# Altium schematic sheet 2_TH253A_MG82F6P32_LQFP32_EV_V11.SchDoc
size 292 x 203 mm
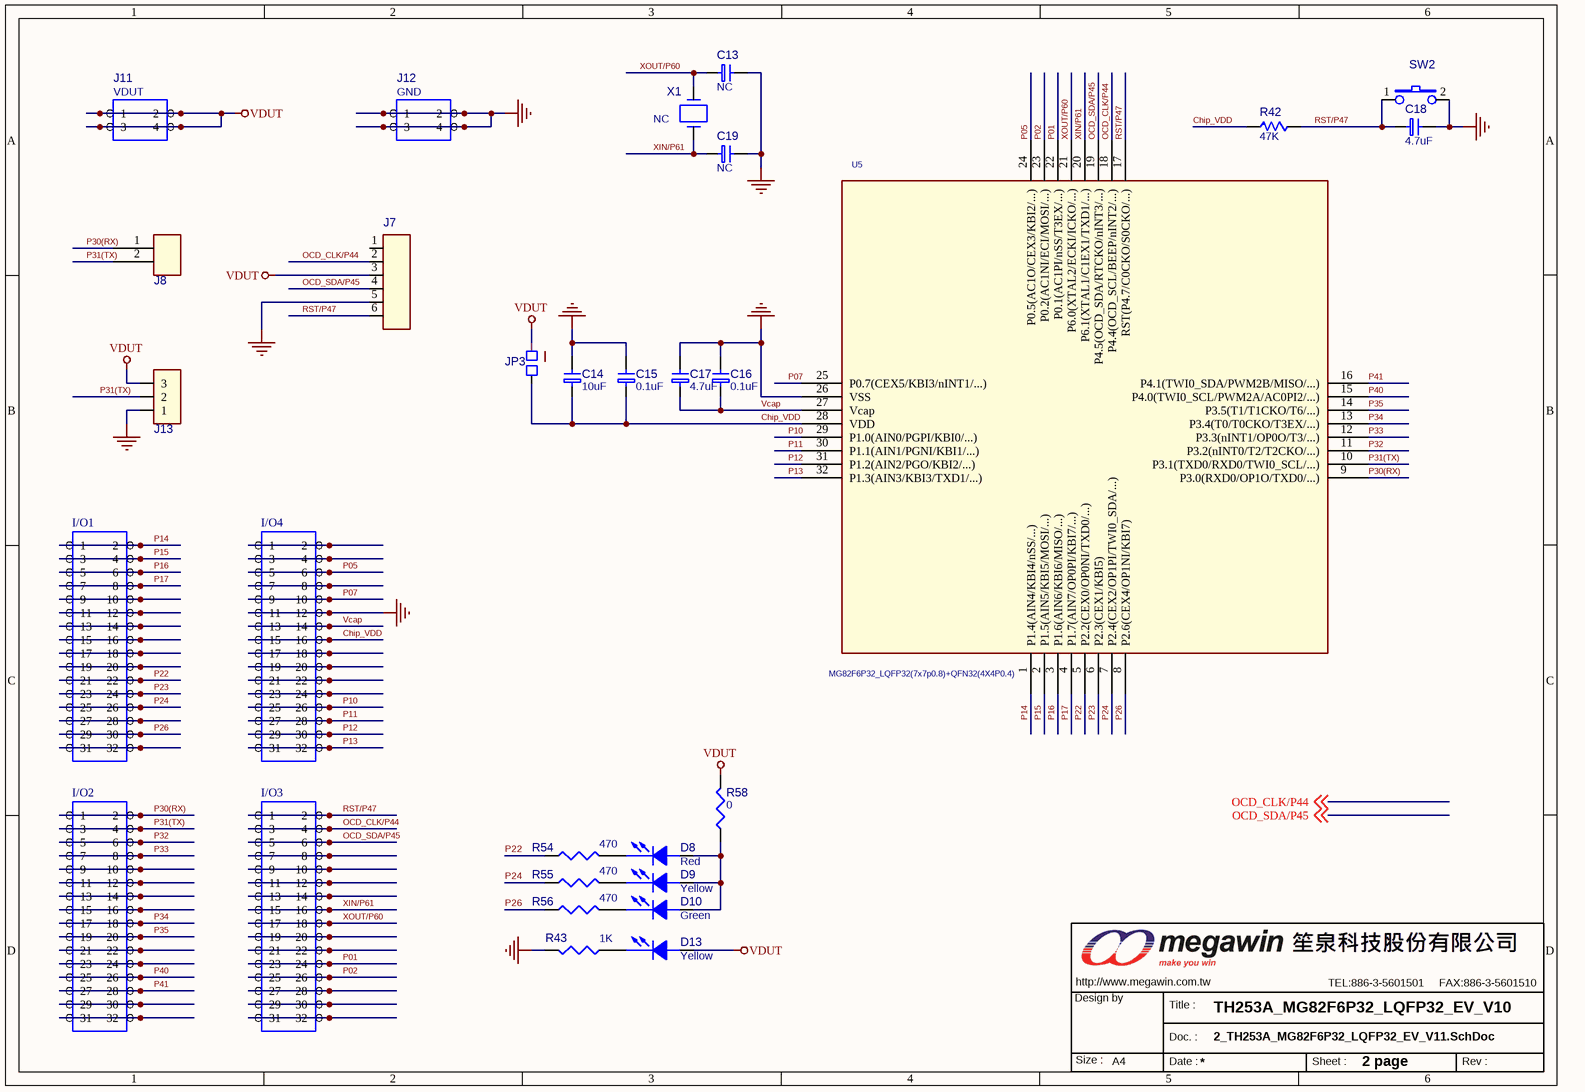
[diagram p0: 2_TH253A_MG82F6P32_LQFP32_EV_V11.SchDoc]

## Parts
C13  NC  [0603C]
C14  10uF  [0603C]
C15  0.1uF  [0603C]
C16  0.1uF  [0603C]
C17  4.7uF  [0603C]
C18  4.7uF  [0603C]
C19  NC  [0603C]
D8  Red  [LED38+0805]
D9  Yellow  [LED38+0805]
D10  Green  [LED38+0805]
D13  Yellow  [0805D]
I/O1  CON16X2  [PS16X2P254]  (value not drawn)
I/O2  CON16X2  [PS16X2P254]  (value not drawn)
I/O3  CON16X2  [PS16X2P254]  (value not drawn)
I/O4  CON16X2  [PS16X2P254]  (value not drawn)
J7  CON6  [PS6P254]  (value not drawn)
J8  NC  [PS2P254]  (value not drawn)
J11  VDUT  [PS2X2P254]
J12  GND  [PS2X2P254]
J13  3P2.54_F_90  [PS3P254f_90]  (value not drawn)
JP3  JUMPER_2  [PS2P254]  (value not drawn)
MW1  OrgAddr3: TEL:886-3-5601501     FAX:886-3-5601510  [MEGAWIN_3.4]  (hidden comment: MW-A4)  (graphical)
R42  47K  [0603R]
R43  1K  [0603R]
R54  470  [0603R]
R55  470  [0603R]
R56  470  [0603R]
R58  0  [PS2p254+0603]
SW2  SW TACT-SPST  [SW_T_2P]  (value not drawn)
U5  MG82F6P32_LQFP32(7x7p0.8)+QFN32(4X4P0.4)  [QFP32_7X7_QFN32_4X4]
X1  NC  [X49U]

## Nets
GND_POWER: C13.2 C14.2 C15.2 C16.2 C17.2 C18.2 C19.2 I/O4.11 I/O4.12 J7.5 J12.1 J12.2 J12.3 J12.4 J13.1 R43.1 SW2.2 U5.26(VSS)
VDUT: D13.1(ANODE) J7.3 J11.1 J11.2 J11.3 J11.4 J13.3 JP3.1 R58.2
Chip_VDD: C14.1 C15.1 I/O4.15 I/O4.16 JP3.2 R42.1 U5.28(VDD)
OCD_CLK/P44: I/O3.3 I/O3.4 J7.2 U5.18(P4.4(OCD_SCL/BEEP/nINT2/...)) ; off-sheet OCD_CLK/P44
OCD_SDA/P45: I/O3.5 I/O3.6 J7.4 U5.19(P4.5(OCD_SDA/RTCKO/nINT3/...)) ; off-sheet OCD_SDA/P45
P01: I/O3.23 I/O3.24 U5.22(P0.1(AC1PI/nSS/T3EX/...))
P02: I/O3.25 I/O3.26 U5.23(P0.2(AC1NI/ECI/MOSI/...))
P05: I/O4.5 I/O4.6 U5.24(P0.5(AC1O/CEX3/KBI2/...))
P07: I/O4.9 I/O4.10 U5.25(P0.7(CEX5/KBI3/nINT1/...))
P10: I/O4.25 I/O4.26 U5.29(P1.0(AIN0/PGPI/KBI0/...))
P11: I/O4.27 I/O4.28 U5.30(P1.1(AIN1/PGNI/KBI1/...))
P12: I/O4.29 I/O4.30 U5.31(P1.2(AIN2/PGO/KBI2/...))
P13: I/O4.31 I/O4.32 U5.32(P1.3(AIN3/KBI3/TXD1/...))
P14: I/O1.1 I/O1.2 U5.1(P1.4(AIN4/KBI4/nSS/...))
P15: I/O1.3 I/O1.4 U5.2(P1.5(AIN5/KBI5/MOSI/...))
P16: I/O1.5 I/O1.6 U5.3(P1.6(AIN6/KBI6/MISO/...))
P17: I/O1.7 I/O1.8 U5.4(P1.7(AIN7/OP0PI/KBI7/...))
P22: I/O1.21 I/O1.22 R54.1 U5.5(P2.2(CEX0/OP0NI/TXD0/...))
P23: I/O1.23 I/O1.24 U5.6(P2.3(CEX1/KBI5))
P24: I/O1.25 I/O1.26 R55.1 U5.7(P2.4(CEX2/OP1PI/TWI0_SDA/...))
P26: I/O1.29 I/O1.30 R56.1 U5.8(P2.6(CEX4/OP1NI/KBI7))
P30(RX): I/O2.1 I/O2.2 J8.1 U5.9(P3.0(RXD0/OP1O/TXD0/...))
P31(TX): I/O2.3 I/O2.4 J8.2 J13.2 U5.10(P3.1(TXD0/RXD0/TWI0_SCL/...))
P32: I/O2.5 I/O2.6 U5.11(P3.2(nINT0/T2/T2CKO/...))
P33: I/O2.7 I/O2.8 U5.12(P3.3(nINT1/OP0O/T3/...))
P34: I/O2.17 I/O2.18 U5.13(P3.4(T0/T0CKO/T3EX/...))
P35: I/O2.19 I/O2.20 U5.14(P3.5(T1/T1CKO/T6/...))
P40: I/O2.25 I/O2.26 U5.15(P4.0(TWI0_SCL/PWM2A/AC0PI2/...))
P41: I/O2.27 I/O2.28 U5.16(P4.1(TWI0_SDA/PWM2B/MISO/...))
RST/P47: C18.1 I/O3.1 I/O3.2 J7.6 R42.2 SW2.1 U5.17(RST(P4.7/C0CKO/S0CKO/...))
Vcap: C16.1 C17.1 I/O4.13 I/O4.14 U5.27(Vcap)
XIN/P61: C19.1 I/O3.15 I/O3.16 U5.20(P6.1(XTAL1/C1EX1/TXD1/...)) X1.2
XOUT/P60: C13.1 I/O3.17 I/O3.18 U5.21(P6.0(XTAL2/ECKI/ICKO/...)) X1.1
NetD8_1: D8.1(ANODE) D9.1(ANODE) D10.1(ANODE) R58.1
NetD8_2: D8.2(CATHODE) R54.2
NetD9_2: D9.2(CATHODE) R55.2
NetD10_2: D10.2(CATHODE) R56.2
NetD13_2: D13.2(CATHODE) R43.2
NetI/O1_9: I/O1.9 I/O1.10
NetI/O1_11: I/O1.11 I/O1.12
NetI/O1_13: I/O1.13 I/O1.14
NetI/O1_15: I/O1.15 I/O1.16
NetI/O1_17: I/O1.17 I/O1.18
NetI/O1_19: I/O1.19 I/O1.20
NetI/O1_27: I/O1.27 I/O1.28
NetI/O1_31: I/O1.31 I/O1.32
NetI/O2_9: I/O2.9 I/O2.10
NetI/O2_11: I/O2.11 I/O2.12
NetI/O2_13: I/O2.13 I/O2.14
NetI/O2_15: I/O2.15 I/O2.16
NetI/O2_21: I/O2.21 I/O2.22
NetI/O2_23: I/O2.23 I/O2.24
NetI/O2_29: I/O2.29 I/O2.30
NetI/O2_31: I/O2.31 I/O2.32
NetI/O3_7: I/O3.7 I/O3.8
NetI/O3_9: I/O3.9 I/O3.10
NetI/O3_11: I/O3.11 I/O3.12
NetI/O3_13: I/O3.13 I/O3.14
NetI/O3_19: I/O3.19 I/O3.20
NetI/O3_21: I/O3.21 I/O3.22
NetI/O3_27: I/O3.27 I/O3.28
NetI/O3_29: I/O3.29 I/O3.30
NetI/O3_31: I/O3.31 I/O3.32
NetI/O4_1: I/O4.1 I/O4.2
NetI/O4_3: I/O4.3 I/O4.4
NetI/O4_7: I/O4.7 I/O4.8
NetI/O4_17: I/O4.17 I/O4.18
NetI/O4_19: I/O4.19 I/O4.20
NetI/O4_21: I/O4.21 I/O4.22
NetI/O4_23: I/O4.23 I/O4.24

Not connected (* = marked no-connect by the designer): J7 1

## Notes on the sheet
- TH253A_MG82F6P32_LQFP32_EV_V10
- 2 page

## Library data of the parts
C13-C19 = CAP: Capacitor
D8-D10 D13 = LED
J7 = CON6_Dup1
J8 = CON2
J11 J12 = CON2X2
J13 = CON3
JP3 = JUMPER_2: Jumper
MW1 = MW_A4_2
R42 = RES1
R43 R54-R56 R58 = R_Dup3
U5 = MG82F6P32_LQFP32
X1 = CRYSTAL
